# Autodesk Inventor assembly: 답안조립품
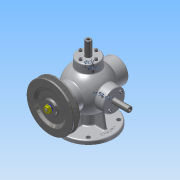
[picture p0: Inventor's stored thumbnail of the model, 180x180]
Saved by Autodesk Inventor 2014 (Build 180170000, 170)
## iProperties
Created: 2016-01
Part Number: 답안조립품
Document SubType Name: Assembly
Designer: Administrator
Mass: 3770.67 g
Surface Area: 2410.99 cm^2
Volume: 903.657 cm^3
Density: 4.17267 g/cm^3
Author: Administrator
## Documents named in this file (17)
- C:\Users\Administrator\Desktop\360108V1002\답안조립품.iam
- C:\Users\Administrator\Desktop\360108V1002\본체.ipt
- C:\Users\Administrator\Desktop\360108V1002\본체커버.ipt
- C:\Users\Administrator\Desktop\360108V1002\베어링- 6202.ipt
- C:\Users\Administrator\Desktop\360108V1002\앞커버.ipt
- C:\Users\Administrator\Desktop\360108V1002\뒤커버.ipt
- C:\Users\Administrator\Desktop\360108V1002\슬라이드 커버.ipt
- C:\Users\Administrator\Desktop\360108V1002\축.ipt
- C:\Users\Administrator\Desktop\360108V1002\오일실.ipt
- C:\Users\Administrator\Desktop\360108V1002\키-4x4.ipt
- C:\Users\Administrator\Desktop\360108V1002\V-벨트풀리.ipt
- C:\Users\Administrator\Desktop\360108V1002\와셔 8x17.ipt
- C:\Users\Administrator\Desktop\360108V1002\너트-M8x1.ipt
- C:\Users\Administrator\Desktop\360108V1002\볼트 M4x0.7.ipt
- C:\Users\Administrator\Desktop\360108V1002\슬라이드.ipt
- C:\Users\Administrator\Desktop\360108V1002\스프링1.ipt
- C:\Users\Administrator\Desktop\360108V1002\스프링2.ipt
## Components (18 placed, 2 different names)
1. V-벨트풀리:1 — 각도:2
2. M4x0.7x12:5
3. M4x0.7x12:1
4. M4x0.7x12:6
5. M4x0.7x12:7
6. M4x0.7x12:8
7. M4x0.7x12:2
8. M4x0.7x12:9
9. M4x0.7x12:10
10. M4x0.7x12:11
11. M4x0.7x12:3
12. M4x0.7x12:12
13. M4x0.7x12:13
14. M4x0.7x12:14
15. M4x0.7x12:4
16. M4x0.7x12:15
17. M4x0.7x12:16
18. M4x0.7x12:17
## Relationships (1: Angle 1)
- 각도:2 [Angle]: V-벨트풀리:1
